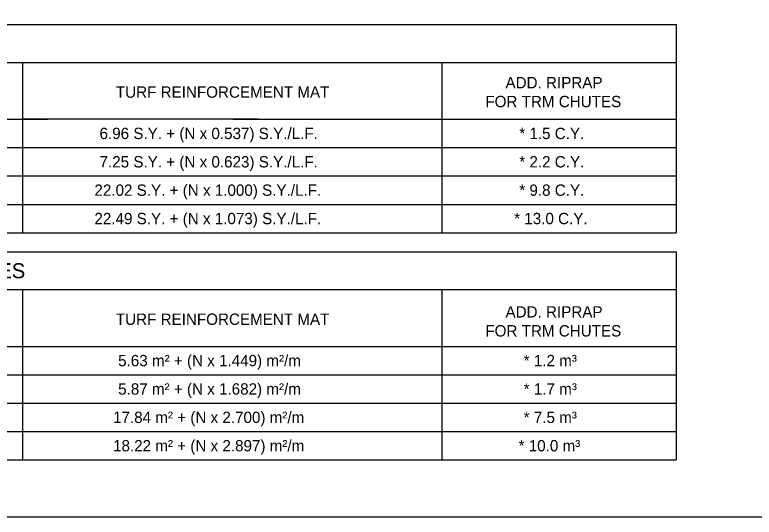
# Model space of a CAD drawing. Extents: x 49991.4 to 50021, y 49987.6 to 50011.4.
# Drawn here: x 50007.078 to 50010.982, y 49987.799 to 49990.455 of the extents above; entities that cross this region are included whole.
import ezdxf

# ---------------------------------------------------------------- set-up
doc = ezdxf.new("R2010")
doc.units = 0
doc.layers.add('Level 1', color=7, linetype='Continuous')
doc.layers.add('Level 2', color=7, linetype='Continuous')

msp = doc.modelspace()

# ---------------------------------------------------------------- linework, layer by layer
at = {"layer": 'Level 1'}
msp.add_lwpolyline([(49999.3835, 49998.9992), (50016.7501, 49998.9992), (50016.7501, 49987.7988), (49999.3835, 49987.7988)], close=True, dxfattribs=at)
at = {"layer": 'Level 2'}
for p, q in [((49999.523, 49990.4027), (50010.5707, 49990.4027)), ((50010.5707, 49990.4027), (50010.5707, 49989.3027)), ((50002.6362, 49990.2027), (50010.5707, 49990.2027)), ((50007.1191, 49990.2027), (50007.1191, 49989.3027)), ((50009.3324, 49990.2027), (50009.3324, 49989.3027)), ((50004.86, 49989.9027), (50007.2509, 49989.9027)), ((50008.3631, 49989.9027), (50007.1191, 49989.9027)), ((50008.2289, 49989.9027), (50010.5707, 49989.9027)), ((49999.523, 49989.7527), (50007.6678, 49989.7527)), ((50007.1191, 49989.7527), (50010.5707, 49989.7527)), ((49999.523, 49989.6027), (50007.6678, 49989.6027)), ((50007.1191, 49989.6027), (50010.5707, 49989.6027)), ((49999.523, 49989.4527), (50007.6678, 49989.4527)), ((50007.1191, 49989.4527), (50010.5707, 49989.4527)), ((49999.523, 49989.3027), (50007.6678, 49989.3027)), ((50007.1191, 49989.3027), (50010.5707, 49989.3027)), ((49999.523, 49989.2018), (50010.5707, 49989.2018)), ((50010.5707, 49989.2018), (50010.5707, 49988.1018)), ((50002.6362, 49989.0018), (50010.5707, 49989.0018)), ((50007.1191, 49989.0018), (50007.1191, 49988.1018)), ((50009.3324, 49989.0018), (50009.3324, 49988.1018)), ((50004.86, 49988.7018), (50007.2509, 49988.7018)), ((50007.1191, 49988.7018), (50010.5707, 49988.7018)), ((49999.523, 49988.5518), (50007.6678, 49988.5518)), ((50007.1191, 49988.5518), (50010.5707, 49988.5518)), ((49999.523, 49988.4018), (50007.6678, 49988.4018)), ((50007.1191, 49988.4018), (50010.5707, 49988.4018)), ((49999.523, 49988.2518), (50007.6678, 49988.2518)), ((50007.1191, 49988.2518), (50010.5707, 49988.2518)), ((49999.523, 49988.1018), (50010.5707, 49988.1018)), ((49999.523, 49988.1018), (50007.6678, 49988.1018))]:
    msp.add_line(p, q, dxfattribs=at)

# ---------------------------------------------------------------- texts
for s, height, p in [('ADD. RIPRAP ', 0.06, (50009.669, 49990.0661)), ('TURF REINFORCEMENT MAT', 0.06, (50007.6117, 49990.0163)), ('FOR TRM CHUTES', 0.06, (50009.5627, 49989.9661)), ('6.96 S.Y. + (N x 0.537) S.Y./L.F.', 0.06, (50007.5255, 49989.7977)), ('* 1.5 C.Y.', 0.06, (50009.7419, 49989.7977)), ('7.25 S.Y. + (N x 0.623) S.Y./L.F.', 0.06, (50007.5255, 49989.6477)), ('* 2.2 C.Y.', 0.06, (50009.7419, 49989.6477)), ('22.02 S.Y. + (N x 1.000) S.Y./L.F.', 0.06, (50007.4985, 49989.4977)), ('* 9.8 C.Y.', 0.06, (50009.7419, 49989.4977)), ('22.49 S.Y. + (N x 1.073) S.Y./L.F.', 0.06, (50007.4985, 49989.3477)), ('* 13.0 C.Y.', 0.06, (50009.7149, 49989.3477)), ('METRIC QUANTITIES', 0.08, (50006.0516, 49989.0618)), ('ADD. RIPRAP ', 0.06, (50009.669, 49988.8541)), ('TURF REINFORCEMENT MAT', 0.06, (50007.6117, 49988.8155)), ('FOR TRM CHUTES', 0.06, (50009.5627, 49988.7541)), ('5.63 m² + (N x 1.449) m²/m', 0.06, (50007.6237, 49988.5968)), ('* 1.2 m³', 0.06, (50009.7652, 49988.5968)), ('5.87 m² + (N x 1.682) m²/m', 0.06, (50007.6237, 49988.4468)), ('* 1.7 m³', 0.06, (50009.7652, 49988.4468)), ('17.84 m² + (N x 2.700) m²/m', 0.06, (50007.5968, 49988.2968)), ('* 7.5 m³', 0.06, (50009.7652, 49988.2968)), ('18.22 m² + (N x 2.897) m²/m', 0.06, (50007.5968, 49988.1468)), ('* 10.0 m³', 0.06, (50009.7383, 49988.1468))]:
    msp.add_text(s, height=height, dxfattribs=at).set_placement(p)

doc.saveas('drawing.dxf')
